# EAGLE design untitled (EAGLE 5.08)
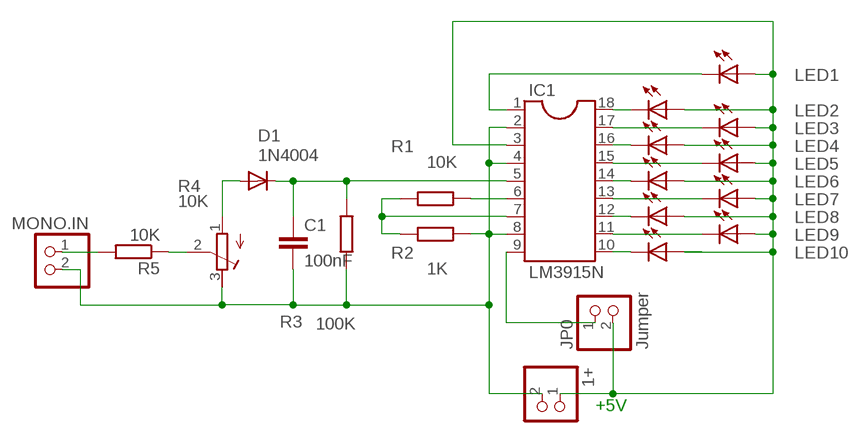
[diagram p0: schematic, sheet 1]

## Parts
1+  PINHD-1X2  [1X02]
C1  100nF  C-EU050-030X075  [C050-030X075]
D1  1N4004  [DO41-10]
IC1  LM3915N  DIL18S  [SOCKET-18]
JP0  Jumper  PINHD-1X2  [1X02]
LED1  LED5MM  [LED5MM]
LED2  LED5MM  [LED5MM]
LED3  LED5MM  [LED5MM]
LED4  LED5MM  [LED5MM]
LED5  LED5MM  [LED5MM]
LED6  LED5MM  [LED5MM]
LED7  LED5MM  [LED5MM]
LED8  LED5MM  [LED5MM]
LED9  LED5MM  [LED5MM]
LED10  LED5MM  [LED5MM]
MONO.IN  PINHD-1X2  [1X02]
R1  10K  R-EU_0207/7  [0207/7]
R2  1K  R-EU_0207/7  [0207/7]
R3  100K  R-EU_0207/7  [0207/7]
R4  10K  R-TRIMM64P  [RTRIM64P]
R5  10K  R-EU_0207/7  [0207/7]

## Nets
N$1: MONO.IN.1 R5.2
N$2: R4.2(S) R5.1
N$3: D1.A R4.1(E)
N$4: C1.1 D1.C IC1.5 R3.2
N$6: IC1.9 JP0.1
N$7: IC1.6 R1.1
N$8: IC1.7 R1.2 R2.2
N$9: 1+.2 C1.2 IC1.2 IC1.4 IC1.8 MONO.IN.2 R2.1 R3.1 R4.3(A)
N$10: 1+.1 IC1.3 JP0.2 LED1.A LED2.A LED3.A LED4.A LED5.A LED6.A LED7.A LED8.A LED9.A LED10.A
N$11: IC1.1 LED1.K(C)
N$12: IC1.18 LED2.K(C)
N$13: IC1.17 LED3.K(C)
N$14: IC1.16 LED4.K(C)
N$15: IC1.15 LED5.K(C)
N$16: IC1.14 LED6.K(C)
N$17: IC1.13 LED7.K(C)
N$18: IC1.12 LED8.K(C)
N$19: IC1.11 LED9.K(C)
N$20: IC1.10 LED10.K(C)

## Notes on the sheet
- +5V

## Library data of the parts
1+ JP0 MONO.IN = pinhead:PINHD-1X2: PIN HEADER
C1 = rcl:C-EU: CAPACITOR, European symbol
D1 = diode:1N4004: DIODE
IC1 = ic-package:DIL18: Dual In Line / Socket
LED1-LED10 = led:LED: LED
R1-R3 R5 = rcl:R-EU_: RESISTOR, European symbol
R4 = rcl:R-TRIMM: Trimm resistor

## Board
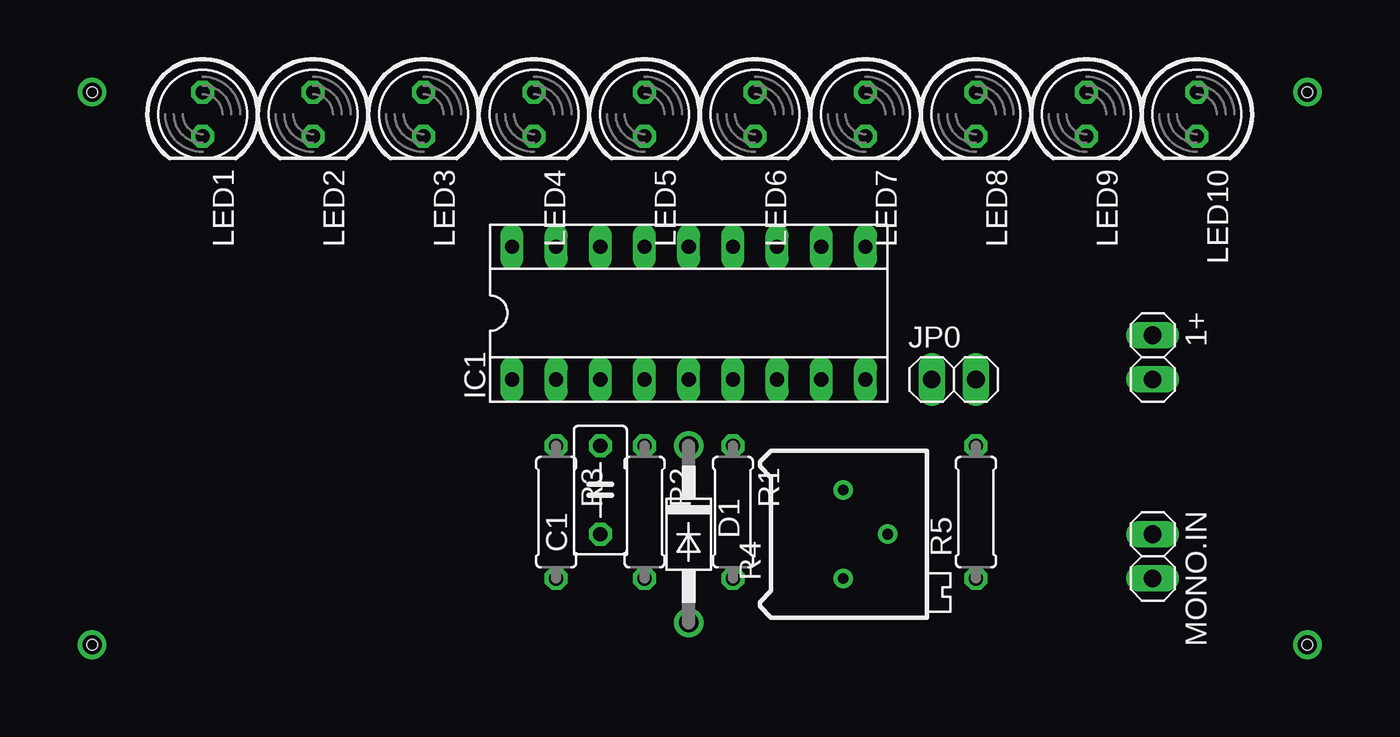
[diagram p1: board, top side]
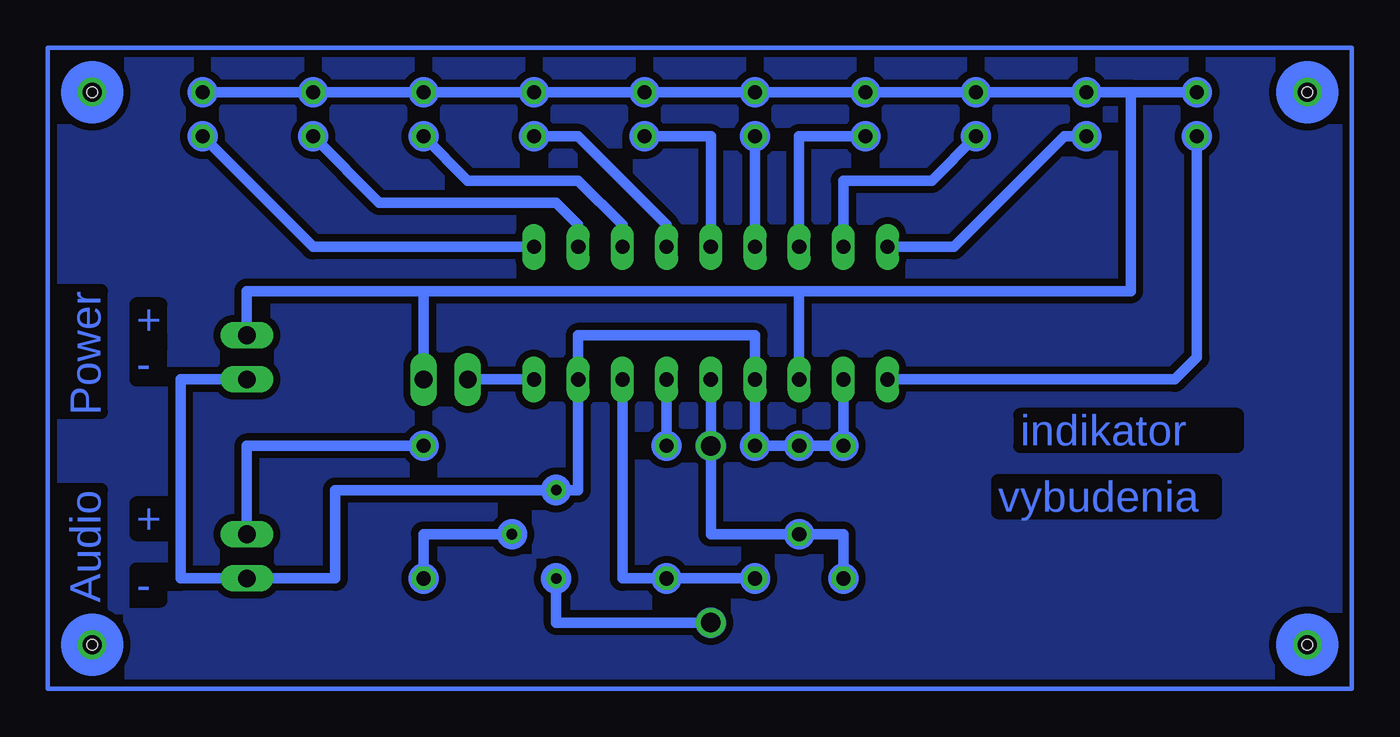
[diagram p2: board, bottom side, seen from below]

No outline drawn. Coordinates in mm, seen from the top.
Copper layers (1*16): Top 0.035mm / dielectric 1.5mm / Bottom 0.035mm
Design rules "default": minimum track width 10mil, minimum drill 24mil, track to track 8mil, track to pad 8mil, pad to pad 8mil, via to via 8mil, smd to smd 8mil, copper to edge 40mil, drill to drill 8mil, minimum pad ring 10mil, minimum via ring 8mil, stop-mask expansion 4mil, vias tented up to drill 0mil, thermal gap 10mil
Holes 0.6 mm at -2.54,45.72 67.31,45.72 67.31,13.97 -2.54,13.97

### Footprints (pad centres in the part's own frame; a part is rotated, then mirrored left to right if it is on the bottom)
1X02 = drill 1.016 long: 1 -1.27,0; 2 1.27,0
C050-030X075 = drill 0.813 octagon: 1 -2.54,0; 2 2.54,0
DO41-10 = drill 1.118 round: A 5.08,0; C -5.08,0
SOCKET-18 = drill 0.813 long: 1 -10.16,-3.81; 2 -7.62,-3.81; 3 -5.08,-3.81; 4 -2.54,-3.81; 5 0,-3.81; 6 2.54,-3.81; 7 5.08,-3.81; 8 7.62,-3.81; 9 10.16,-3.81; 10 10.16,3.81; 11 7.62,3.81; 12 5.08,3.81; 13 2.54,3.81; 14 0,3.81; 15 -2.54,3.81; 16 -5.08,3.81; 17 -7.62,3.81; 18 -10.16,3.81
LED5MM = drill 0.813 octagon: A -1.27,0; K 1.27,0
0207/7 = drill 0.813 octagon: 1 -3.81,0; 2 3.81,0
RTRIM64P = drill 0.61 round: 1 0,-2.54; 2 2.54,0; 3 0,2.54

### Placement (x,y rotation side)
1+  58.42,30.48 270 top
C1  26.67,22.86 90 top
D1  31.75,20.32 270 top
IC1  31.75,33.02 0 top
JP0  46.99,29.21 0 top
LED1  3.81,44.45 270 top
LED2  10.16,44.45 270 top
LED3  16.51,44.45 270 top
LED4  22.86,44.45 270 top
LED5  29.21,44.45 270 top
LED6  35.56,44.45 270 top
LED7  41.91,44.45 270 top
LED8  48.26,44.45 270 top
LED9  54.61,44.45 270 top
LED10  60.96,44.45 270 top
MONO.IN  58.42,19.05 270 top
R1  34.29,21.59 270 top
R2  29.21,21.59 270 top
R3  24.13,21.59 270 top
R4  40.64,20.32 0 top
R5  48.26,21.59 90 top

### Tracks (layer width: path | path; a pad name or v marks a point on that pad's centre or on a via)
N$1
  Bottom 0.61: R5.2 58.42,25.4 MONO.IN.1
N$2
  Bottom 0.61: R4.2 48.26,20.32 R5.1
N$3
  Bottom 0.61: D1.A 40.64,15.24 R4.1
N$4
  Bottom 0.61: IC1.5 D1.C 31.75,20.32 C1.1 24.13,20.32 R3.2
N$5
  Bottom 0.254: -5.08,48.26 69.85,48.26 69.85,11.43 -5.08,11.43 -5.08,48.26
N$6
  Bottom 0.61: IC1.9 JP0.1
N$7
  Bottom 0.61: R1.1 IC1.6
N$8
  Bottom 0.61: R2.2 R1.2 36.83,17.78 IC1.7
N$9
  Bottom 0.61: IC1.2 R3.1 C1.2 R2.1 IC1.4 29.21,31.75 39.37,31.75 IC1.8 39.37,22.86 R4.3 53.34,22.86 53.34,17.78 MONO.IN.2 62.23,17.78 62.23,29.21 1+.2
N$10
  Bottom 0.61: 7.62,45.72 LED1.A | 7.62,45.72 LED2.A LED3.A LED4.A LED5.A LED6.A LED7.A LED8.A LED9.A LED10.A | 26.67,34.29 IC1.3 | 26.67,34.29 7.62,34.29 7.62,45.72 | 26.67,34.29 48.26,34.29 | 48.26,34.29 58.42,34.29 1+.1 | 48.26,34.29 JP0.2
N$11
  Bottom 0.61: LED1.K 3.81,30.48 5.08,29.21 IC1.1
N$12
  Bottom 0.61: IC1.18 17.78,36.83 11.43,43.18 LED2.K
N$13
  Bottom 0.61: LED3.K 19.05,40.64 24.13,40.64 IC1.17
N$14
  Bottom 0.61: LED4.K 26.67,43.18 IC1.16
N$15
  Bottom 0.61: IC1.15 LED5.K
N$16
  Bottom 0.61: LED6.K 31.75,43.18 IC1.14
N$17
  Bottom 0.61: LED7.K 39.37,43.18 34.29,38.1 IC1.13
N$18
  Bottom 0.61: LED8.K 45.72,40.64 39.37,40.64 36.83,38.1 IC1.12
N$19
  Bottom 0.61: IC1.11 39.37,38.1 40.64,39.37 50.8,39.37 LED9.K
N$20
  Bottom 0.61: LED10.K 54.61,36.83 IC1.10
N$21  (via drill 1.1)
  other vias: -2.54,45.72
N$22  (via drill 1.1)
  other vias: -2.54,13.97
N$23  (via drill 1.1)
  other vias: 67.31,45.72
N$24  (via drill 1.1)
  other vias: 67.31,13.97
N$25
  pour Bottom (isolate 0.406): -5.08,48.01 69.85,48.01 69.85,11.43 -5.08,11.43
(copper drawn outside any net)
  shapes: Bottom circle x39

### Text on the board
Bottom: Power | + | - | indikator | Audio | vybudenia | + | -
